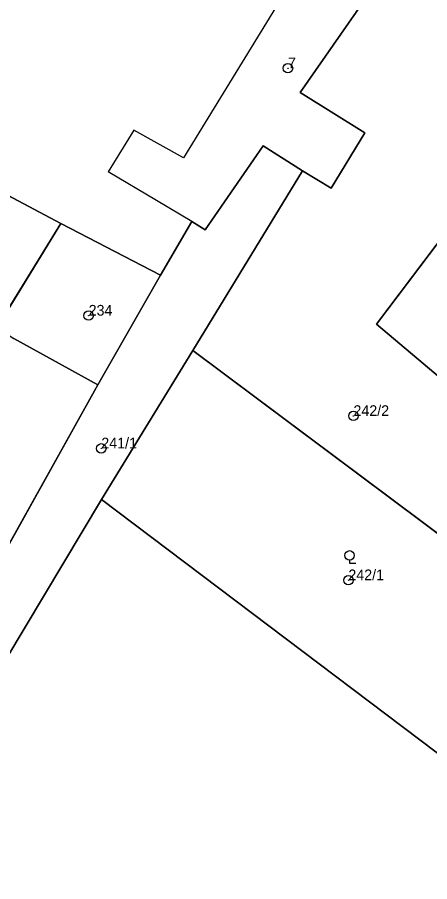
# Model space of a CAD drawing. Extents: x -652854 to -650068, y -1097661 to -1095417.
# Drawn here: x -651004.4 to -650938.6, y -1096137.1 to -1095999.2 of the extents above; entities that cross this region are included whole.
import ezdxf

# ---------------------------------------------------------------- set-up
doc = ezdxf.new("R2010")
doc.units = 0
for name, color, linetype in [('Definiční body parcel', 7, 'Continuous'), ('Hranice - vnitř_ kresba', 7, 'Continuous'), ('Hranice parcel', 7, 'Continuous'), ('Obvody jako plochy', 7, 'Continuous'), ('Parcelní čísla', 7, 'Continuous'), ('Značky kultur', 7, 'Continuous')]:
    doc.layers.add(name, color=color, linetype=linetype)

msp = doc.modelspace()

# ---------------------------------------------------------------- linework, layer by layer
at = {"layer": 'Definiční body parcel'}
for centre, radius in [((-650961.2, -1096007.35), 0.75), ((-650961.2, -1096007.35), 0.0327), ((-650993.01, -1096046.79), 0.75), ((-650993.01, -1096046.79), 0.0327), ((-650950.75, -1096062.79), 0.75), ((-650950.75, -1096062.79), 0.0327), ((-650990.99, -1096067.96), 0.75), ((-650990.99, -1096067.96), 0.0327), ((-650951.56, -1096088.98), 0.75), ((-650951.56, -1096088.98), 0.0327)]:
    msp.add_circle(centre, radius, dxfattribs=at)
at = {"layer": 'Hranice - vnitř_ kresba'}
for p, q in [((-650956.46, -1095986.73), (-650977.88, -1096021.61)), ((-650985.8, -1096017.2), (-650989.88, -1096023.87)), ((-650977.88, -1096021.61), (-650985.8, -1096017.2)), ((-650982.19, -1096028.42), (-650989.88, -1096023.87)), ((-650976.56, -1096031.8), (-650982.19, -1096028.42))]:
    msp.add_line(p, q, dxfattribs=at)
at = {"layer": 'Hranice parcel'}
for p, q in [((-650959.24, -1096011.23), (-650946.25, -1095992.54)), ((-650948.93, -1096017.64), (-650959.24, -1096011.23)), ((-650997.45, -1096032.13), (-651031.54, -1096014.05)), ((-650954.29, -1096026.46), (-650948.93, -1096017.64)), ((-650974.42, -1096033.09), (-650965.14, -1096019.73)), ((-650965.14, -1096019.73), (-650958.9, -1096023.69)), ((-650926.24, -1096020.58), (-650947.07, -1096048.17)), ((-650976.4, -1096052.35), (-650958.9, -1096023.69)), ((-650958.9, -1096023.69), (-650954.29, -1096026.46)), ((-650981.53, -1096040.37), (-650976.56, -1096031.8)), ((-650974.42, -1096033.09), (-650976.56, -1096031.8)), ((-651007.66, -1096048.68), (-650997.45, -1096032.13)), ((-650997.45, -1096032.13), (-650981.53, -1096040.37)), ((-650991.56, -1096057.81), (-650981.53, -1096040.37)), ((-650947.07, -1096048.17), (-650935.88, -1096057.57)), ((-651004.94, -1096050.45), (-650991.56, -1096057.81)), ((-650990.95, -1096076.09), (-650976.4, -1096052.35)), ((-650923.91, -1096091.54), (-650976.4, -1096052.35)), ((-651014.14, -1096098.31), (-650991.56, -1096057.81)), ((-651009.35, -1096106.79), (-650990.95, -1096076.09)), ((-650913.45, -1096134.6), (-650990.95, -1096076.09))]:
    msp.add_line(p, q, dxfattribs=at)
at = {"layer": 'Obvody jako plochy'}
for points in [[(-650933.62, -1096190.95), (-650913.45, -1096134.6), (-650990.95, -1096076.09), (-651009.35, -1096106.79), (-651010.55, -1096105.82), (-651030.5, -1096133.13), (-651070.99, -1096111.17), (-651084.01, -1096101.86), (-651087.49, -1096100.27), (-651097.64, -1096121.44), (-651165.97, -1096079.02), (-651156.45, -1096060.87), (-651099.24, -1095958.6), (-651062.2, -1095980.68), (-651049.83, -1095974.3), (-651066.45, -1095946.35), (-651086.96, -1095898.16), (-651112.56, -1095892.68), (-651141.79, -1095892.88), (-651224.65, -1095909.2), (-651256.73, -1095919.7), (-651301.18, -1095941.4)], [(-651031.54, -1096014.05), (-650997.45, -1096032.13), (-650981.53, -1096040.37), (-650976.56, -1096031.8), (-650974.42, -1096033.09), (-650965.14, -1096019.73), (-650958.9, -1096023.69), (-650954.29, -1096026.46), (-650948.93, -1096017.64), (-650959.24, -1096011.23), (-650946.25, -1095992.54), (-650956.46, -1095986.73), (-650968.76, -1095970.97), (-651011.17, -1095949.81)], [(-651014.14, -1096098.31), (-650991.56, -1096057.81), (-651004.94, -1096050.45)]]:
    msp.add_lwpolyline(points, dxfattribs=at)
for points in [[(-650928.95, -1095991.79), (-650941.58, -1095987.24), (-650943.99, -1095992.27), (-650946.25, -1095992.54), (-650959.24, -1096011.23), (-650948.93, -1096017.64), (-650954.29, -1096026.46), (-650958.9, -1096023.69), (-650976.4, -1096052.35), (-650923.91, -1096091.54), (-650915.34, -1096072.03), (-650914.12, -1096069.22), (-650936.73, -1096059.52), (-650935.88, -1096057.57), (-650947.07, -1096048.17), (-650926.24, -1096020.58), (-650927.6, -1096019.54), (-650929.8, -1096017.97), (-650930.14, -1096005.05), (-650934.27, -1095994.75), (-650932.24, -1095992.24)], [(-651031.54, -1096014.05), (-651038.59, -1096025.68), (-651043.36, -1096022.88), (-651046.49, -1096028.08), (-651047.38, -1096029.56), (-651054.82, -1096041.58), (-651044.45, -1096047.83), (-651053.23, -1096062.86), (-651056.1, -1096061.61), (-651058.49, -1096065.31), (-651055.5, -1096067.11), (-651061.54, -1096076.57), (-651059.8, -1096077.59), (-651046.21, -1096085.02), (-651033.7, -1096092.48), (-651016.5, -1096063.88), (-651028.45, -1096056.8), (-651035.68, -1096052.5), (-651028.03, -1096039.18), (-651008.97, -1096050.36), (-651007.66, -1096048.68), (-650997.45, -1096032.13)], [(-650991.56, -1096057.81), (-651014.14, -1096098.31), (-651032.76, -1096127.64), (-651083.41, -1096100.58), (-651084.01, -1096101.86), (-651070.99, -1096111.17), (-651030.5, -1096133.13), (-651010.55, -1096105.82), (-651009.35, -1096106.79), (-650990.95, -1096076.09), (-650976.4, -1096052.35), (-650958.9, -1096023.69), (-650965.14, -1096019.73), (-650974.42, -1096033.09), (-650976.56, -1096031.8), (-650981.53, -1096040.37)], [(-650926.24, -1096020.58), (-650947.07, -1096048.17), (-650935.88, -1096057.57), (-650929.43, -1096042.79), (-650926.04, -1096038.44), (-650922.29, -1096036.66), (-650916.32, -1096038.32), (-650904.71, -1096047.58), (-650888.23, -1096060.47), (-650885.56, -1096063.83), (-650884.57, -1096069.52), (-650874.66, -1096043.25), (-650875.54, -1096045.04), (-650878.99, -1096052.02), (-650882.38, -1096052.68), (-650886.47, -1096051.45), (-650905.32, -1096036.52)], [(-651004.94, -1096050.45), (-650991.56, -1096057.81), (-650981.53, -1096040.37), (-650997.45, -1096032.13), (-651007.66, -1096048.68)], [(-650990.95, -1096076.09), (-650913.45, -1096134.6), (-650902.95, -1096107.33), (-650913.85, -1096098.99), (-650924.96, -1096093.93), (-650923.91, -1096091.54), (-650976.4, -1096052.35)]]:
    msp.add_lwpolyline(points, close=True, dxfattribs=at)
at = {"layer": 'Značky kultur'}
for p, q in [((-650951.37, -1096085.77), (-650951.37, -1096086.27)), ((-650951.37, -1096086.27), (-650950.347, -1096086.27))]:
    msp.add_line(p, q, dxfattribs=at)
msp.add_circle((-650951.37, -1096085.02), 0.75, dxfattribs=at)

# ---------------------------------------------------------------- texts
at = {"layer": 'Parcelní čísla'}
for s, p in [('7', (-650961.2, -1096007.35)), ('234', (-650993.01, -1096046.79)), ('242/2', (-650950.75, -1096062.79)), ('241/1', (-650990.99, -1096067.96)), ('242/1', (-650951.56, -1096088.98))]:
    msp.add_text(s, height=1.7, dxfattribs=at).set_placement(p)

doc.saveas('drawing.dxf')
